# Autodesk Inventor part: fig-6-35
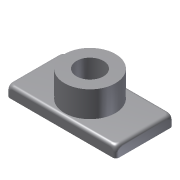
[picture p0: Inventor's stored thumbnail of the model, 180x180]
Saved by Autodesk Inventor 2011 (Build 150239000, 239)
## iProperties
Created: 2004-05
Part Number: fig-6-35
Document SubType Name: Modeling
Designer: CADCIM Technologies
Manufacturer: Standard
Standards Organization: Custom
Density: 1 g/cm^3
Author: CADCIM Technologies
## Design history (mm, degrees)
sketch "Sketch1"
  geometry: L1 (-39.276, -18.692)-(33.721, -18.692); L2 (33.721, -18.692)-(33.721, 19.728); L3 (33.721, 19.728)-(-39.276, 19.728); L4 (-39.276, 19.728)-(-39.276, -18.692)
  constraints: 8 end point, 2 parallel, 1 horizontal, 1 perpendicular
extrude "Extrusion1" new body sketch "Sketch1" distance "d0" = 7.5; taper "d1" = 0 deg
sketch "Sketch2"
  geometry: C1 r 17 at (-2.778, 0.518)
  constraints: 1 centre point
  dimensions: "d16" = 34 diameter of C1
extrude "Extrusion2" join sketch "Sketch2" distance "d3" = 17.25; taper "d4" = 0 deg
hole "Hole1" diameter "d8" = 18; stored, may be unused: countersink angle "d12" = 90 deg, drill point angle "d14" = 118 deg; dims "d6" = 10, "d7" = 10, "d9" = 6, "d10" = 4, "d11" = 2, "d13" = 8
fillet "Fillet4" dims "d17" = 2
body "Solid1"
